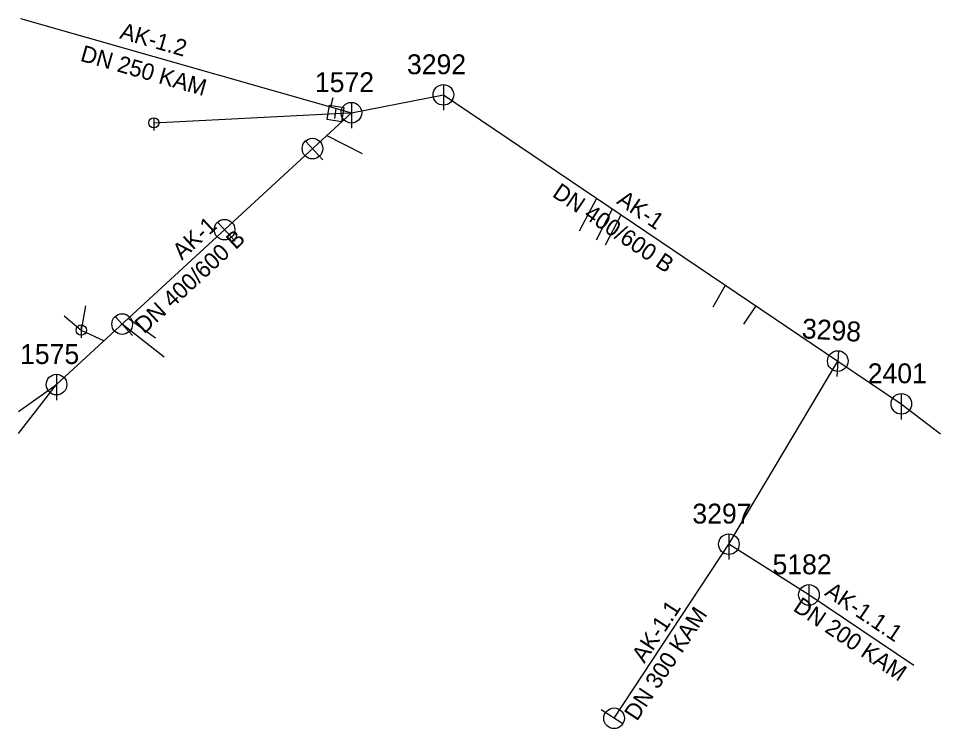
# Model space of a CAD drawing. Extents: x -496908.3 to -496818.9, y -1087768.9 to -1087699.7.
import ezdxf

# ---------------------------------------------------------------- set-up
doc = ezdxf.new("R2010")
doc.units = 0
for name, color, linetype in [('_pripojka_kanal_destova_priblizne_', 7, 'Continuous'), ('_pripojka_kanal_jednotna_priblizne_', 7, 'Continuous'), ('_pripojka_kanal_splaskova_priblizne_', 7, 'Continuous'), ('_stoka_jednotna_smvak_prevzato_z_dokumentace_', 7, 'Continuous'), ('Default', 7, 'Continuous'), ('MoLevel 119', 7, 'Continuous'), ('MoLevel 120', 7, 'Continuous'), ('MoLevel 57', 7, 'Continuous'), ('MoLevel 63', 7, 'Continuous'), ('MoLevel 68', 7, 'Continuous'), ('MoLevel 69', 7, 'Continuous')]:
    doc.layers.add(name, color=color, linetype=linetype)

# ---------------------------------------------------------------- blocks, each defined once
blk = doc.blocks.new('_vpust_')
at = {"layer": 'Default'}
blk.add_line((0, 0.000025), (0, -0.000025), dxfattribs=at)
blk.add_lwpolyline([(-0.000035, 0.000035), (0.000035, 0.000035), (0.000035, -0.000035), (-0.000035, -0.000035), (-0.000035, 0.000035)], dxfattribs=at)
blk = doc.blocks.new('_sachta_kanal_prip_')
at = {"layer": 'Default'}
blk.add_line((0, 0.00005), (0, -0.000075), dxfattribs=at)
blk.add_circle((0, 0), 0.00005, dxfattribs=at)
blk = doc.blocks.new('_sachta_kanal_prevzato_z_dokumentace_')
at = {"layer": 'Default'}
blk.add_line((0, 0.00005), (0, -0.000075), dxfattribs=at)
blk.add_circle((0, 0), 0.00005, dxfattribs=at)

msp = doc.modelspace()

# ---------------------------------------------------------------- linework, layer by layer
at = {"layer": '_pripojka_kanal_destova_priblizne_'}
for p, q in [((-496895.131, -1087709.802), (-496877.531, -1087708.902)), ((-496877.531, -1087708.902), (-496875.989, -1087708.823)), ((-496903.83, -1087728.51), (-496902.165, -1087729.895)), ((-496908.254, -1087737.799), (-496904.564, -1087735.186))]:
    msp.add_line(p, q, dxfattribs=at)
at = {"layer": '_pripojka_kanal_jednotna_priblizne_'}
for p, q in [((-496877.775, -1087707.379), (-496878.019, -1087708.26)), ((-496874.9, -1087712.804), (-496878.398, -1087711.045)), ((-496853.867, -1087720.283), (-496852.212, -1087717.121)), ((-496852.236, -1087721.155), (-496850.687, -1087718.15)), ((-496851.365, -1087721.647), (-496849.852, -1087718.714)), ((-496840.939, -1087727.636), (-496839.724, -1087725.553)), ((-496837.955, -1087729.317), (-496836.773, -1087727.545)), ((-496894.977, -1087730.68), (-496897.606, -1087728.767)), ((-496902.165, -1087729.895), (-496899.95, -1087730.929)), ((-496894.146, -1087732.526), (-496898.202, -1087729.316)), ((-496850.306, -1087767.677), (-496850.522, -1087767.535))]:
    msp.add_line(p, q, dxfattribs=at)
at = {"layer": '_pripojka_kanal_splaskova_priblizne_'}
msp.add_line((-496901.749, -1087727.551), (-496902.165, -1087729.895), dxfattribs=at)
at = {"layer": '_stoka_jednotna_smvak_prevzato_z_dokumentace_'}
for p, q in [((-496908.06, -1087699.68), (-496875.989, -1087708.823)), ((-496875.989, -1087708.823), (-496867.068, -1087707.09)), ((-496867.068, -1087707.09), (-496828.846, -1087732.898)), ((-496904.564, -1087735.186), (-496875.989, -1087708.823)), ((-496839.405, -1087750.656), (-496828.846, -1087732.898)), ((-496828.846, -1087732.898), (-496822.691, -1087737.054)), ((-496908.254, -1087739.928), (-496904.564, -1087735.186)), ((-496822.691, -1087737.054), (-496818.887, -1087739.948)), ((-496850.525, -1087767.539), (-496839.405, -1087750.656)), ((-496831.639, -1087755.573), (-496839.405, -1087750.656)), ((-496821.478, -1087762.403), (-496831.639, -1087755.573))]:
    msp.add_line(p, q, dxfattribs=at)

# ---------------------------------------------------------------- block references
at = {"layer": 'MoLevel 119', "xscale": 20000, "yscale": 20000}
for p in [(-496867.067, -1087707.089), (-496875.989, -1087708.823), (-496904.564, -1087735.185), (-496822.689, -1087737.052), (-496839.405, -1087750.655), (-496831.639, -1087755.573)]:
    msp.add_blockref('_sachta_kanal_prevzato_z_dokumentace_', p, dxfattribs=at)
at = {"layer": 'MoLevel 119', "xscale": 20000}
for p, yscale, rotation in [((-496879.759, -1087712.301), 20000, 42.69431280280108), ((-496888.279, -1087720.161), 20000, 42.694312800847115), ((-496898.202, -1087729.316), 20000, 42.691823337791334), ((-496828.846, -1087732.898), 19999.999999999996, -3.5130717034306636), ((-496850.525, -1087767.538), 20000.000000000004, -122.7845214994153)]:
    msp.add_blockref('_sachta_kanal_prevzato_z_dokumentace_', p, dxfattribs=dict(at, yscale=yscale, rotation=rotation))
at = {"layer": 'MoLevel 57', "xscale": 10000, "yscale": 10000}
for p in [(-496895.131, -1087709.802), (-496902.165, -1087729.895)]:
    msp.add_blockref('_sachta_kanal_prip_', p, dxfattribs=at)
at = {"layer": 'MoLevel 63', "xscale": 20000, "yscale": 20000, "rotation": 171.34183518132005}
msp.add_blockref('_vpust_', (-496877.531, -1087708.902), dxfattribs=at)

# ---------------------------------------------------------------- texts
at = {"layer": 'MoLevel 120'}
for s, p in [('3292', (-496870.598, -1087705.089)), ('1572', (-496879.52, -1087706.823)), ('1575', (-496908.095, -1087733.185)), ('2401', (-496825.945, -1087735.052)), ('3297', (-496842.936, -1087748.655)), ('5182', (-496835.17, -1087753.573))]:
    msp.add_text(s, height=1.9259, dxfattribs=at).set_placement(p)
msp.add_text('3298', height=1.9259, rotation=356.48693, dxfattribs=at).set_placement((-496832.37, -1087730.682))
at = {"layer": 'MoLevel 68'}
for s, height, rotation, p in [('DN 250 KAM', 1.6049, 344.08789, (-496902.345, -1087703.778)), ('DN 400/600 B', 1.60494, 325.97226, (-496856.614, -1087716.885)), ('DN 400/600 B', 1.60494, 42.69431, (-496896.069, -1087730.332)), ('DN 200 KAM', 1.6049, 326.08942, (-496833.271, -1087757.031)), ('DN 300 KAM', 1.6049, 56.63006, (-496848.308, -1087767.891))]:
    msp.add_text(s, height=height, rotation=rotation, dxfattribs=at).set_placement(p)
at = {"layer": 'MoLevel 69'}
for s, rotation, p in [('AK-1.2', 344.08789, (-496898.524, -1087701.599)), ('AK-1', 325.97226, (-496850.364, -1087717.569)), ('AK-1', 42.69431, (-496892.411, -1087723.174)), ('AK-1.1.1', 326.08942, (-496830.219, -1087755.549)), ('AK-1.1', 56.63006, (-496847.588, -1087762.28))]:
    msp.add_text(s, height=1.6049, rotation=rotation, dxfattribs=at).set_placement(p)

doc.saveas('drawing.dxf')
